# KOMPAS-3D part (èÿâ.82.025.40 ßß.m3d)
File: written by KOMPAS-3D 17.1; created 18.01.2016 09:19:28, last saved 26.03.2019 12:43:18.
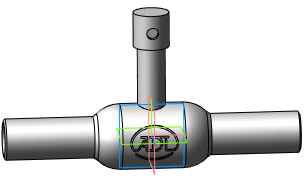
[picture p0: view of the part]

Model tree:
1. Операция без истории:6  (labels: Сталь 20  ГОСТ 1050-88)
